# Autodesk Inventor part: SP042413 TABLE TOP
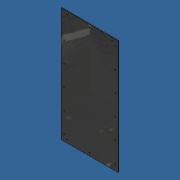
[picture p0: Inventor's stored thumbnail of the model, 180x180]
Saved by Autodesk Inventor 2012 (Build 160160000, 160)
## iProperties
Created: 2013-04
Part Number: SP042413 TABLE TOP
Material: UHMW, Black
Document SubType Name: Modeling
Designer: Admin
Mass: 19963.4 g
Surface Area: 34141.9 cm^2
Volume: 21237.6 cm^3
Density: 0.94 g/cm^3
Author: Admin
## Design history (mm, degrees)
sketch "Sketch1"
  geometry: L1 (-457.2, 914.4)-(457.2, 914.4); L2 (457.2, 914.4)-(457.2, -914.4); L3 (457.2, -914.4)-(-457.2, -914.4); L4 (-457.2, -914.4)-(-457.2, 914.4); 3 further points
  constraints: 8 end point, 2 midpoint, 2 parallel, 1 horizontal, 1 horizontal alignment, 1 perpendicular, 1 vertical alignment
  dimensions: "d0" = 914.4 distance of L1.start L1.end (= DEPTH); "d1" = 1828.8 distance of L3.end L1.start (= Width)
extrude "Extrusion1" new body sketch "Sketch1" distance "d2" = 12.7 (= TABLE_TOP_THICKNESS); taper "d3" = 0 deg
fillet "Fillet1" dims "d4" = 8.46667 (= 0.333333 x TOP_OVERHANG)
sketch "Sketch2"
  geometry: L1 (448.733, -914.4)-(-448.733, -914.4) reference; L2 (457.2, 905.933)-(457.2, -905.933) reference; L3 (-448.733, 914.4)-(448.733, 914.4) reference; L4 (-457.2, -905.933)-(-457.2, 905.933) reference; 19 further points
  constraints: 11 vertical alignment, 8 horizontal alignment
  dimensions: "d5" = 47.9 distance from line of point (-409.3, -812.8) L4 (computed from TOP_OVERHANG); "d6" = 47.9 distance from line of point (409.3, -812.8) L2 (computed from TOP_OVERHANG); "d7" = 47.9 distance from line of point (0, -866.5) L1 (computed from TOP_OVERHANG); "d8" = 47.9 distance from line of point (0, 866.5) L3 (computed from TOP_OVERHANG); "d9" = 101.6 distance from line of point (355.6, 866.5) L2 (computed from TOP_OVERHANG); "d10" = 101.6 distance from line of point (-355.6, 866.5) L4 (= d9); "d11" = 101.6 distance from line of point (409.3, 812.8) L3 (= d9); "d12" = 101.6 distance from line of point (-409.3, 812.8) L3 (= d10); "d13" = 101.6 distance from line of point (409.3, -812.8) L1 (= d11); "d14" = 101.6 distance from line of point (355.6, -866.5) L2 (= d13); "d15" = 101.6 distance from line of point (-355.6, -866.5) L4 (= d14); "d16" = 101.6 distance from line of point (-409.3, -812.8) L1 (= d13); "d17" = 711.2 distance of point (-355.6, -866.5) point (355.6, -866.5) (derived); "d18" = 355.6 distance of point (0, -866.5) point (355.6, -866.5) (= 0.5 x d17); "d19" = 1625.6 distance of point (409.3, -812.8) point (409.3, 812.8) (derived); "d20" = 325.12 distance of point (409.3, 487.68) point (409.3, 812.8) (= 0.2 x d19); "d21" = 325.12 distance of point (409.3, 162.56) point (409.3, 487.68) (= d20); "d22" = 325.12 distance of point (409.3, -162.56) point (409.3, 162.56) (= d21); "d23" = 325.12 distance of point (409.3, -487.68) point (409.3, -162.56) (= d22)
hole "Hole1" sketch "Sketch2" at (409.3, -812.8), (355.6, -866.5), (-355.6, -866.5), (-409.3, -812.8), (-409.3, 812.8), (-355.6, 866.5), (355.6, 866.5), (409.3, 812.8), (409.3, 487.68), (409.3, 162.56), (409.3, -162.56), (409.3, -487.68)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 diameter "d24" = 6.5; stored, may be unused: countersink angle "d28" = 90 deg, drill point angle "d30" = 118 deg; dims "d25" = 19.05, "d26" = 14, "d27" = 6.35, "d29" = 25.4
fillet "Fillet2" dims "d31" = 6.35
body "Solid1"
other parameters: "Height" = 1066.8 [user parameter], "Width" = 1828.8 [user parameter; used in 1 equation term], "DEPTH" = 914.4 [user parameter; used in 1 equation term], "LOWER_INSET" = 203.2 [user parameter], "TABLE_TOP_THICKNESS" = 12.7 [user parameter; used in 1 equation term], "LEVELER_HEIGHT" = 115.824 [user parameter], "TOP_OVERHANG" = 25.4 [user parameter; used in 6 equation terms]
